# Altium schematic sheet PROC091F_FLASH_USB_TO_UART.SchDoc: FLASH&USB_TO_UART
size 431 x 279 mm; Date: Not shown in title block; ApprovedBy: Not shown in title block; CheckedBy: Not shown in title block; Author: Not shown in title block; CompanyName: Not shown in title block; DrawnBy: Antony/Bala; Engineer: Not shown in title block; Organization: Not shown in title block; Address1: Not shown in title block; Address2: Not shown in title block; Address3: Not shown in title block; Address4: Not shown in title block; DocumentNumber: 6; Revision: Use project parameter SCH_Rev; SheetNumber: 6; SheetTotal: 12; PageSetup: Record=PageOptions¦CenterHorizontal=True¦CenterVertical=True¦PrintScale=1.00¦XCorrection=1.00¦YCorrection=1.00¦PrintKind=0¦BorderSize=5000000¦LeftOffset=0¦BottomOffset=0¦Orientation=2¦PaperLength=1000¦PaperWidth=1000¦Scale=100¦PaperSource=15¦PrintQuality=600¦MediaType=1¦DitherType=10¦PaperKind=Letter¦PrintScaleMode=1
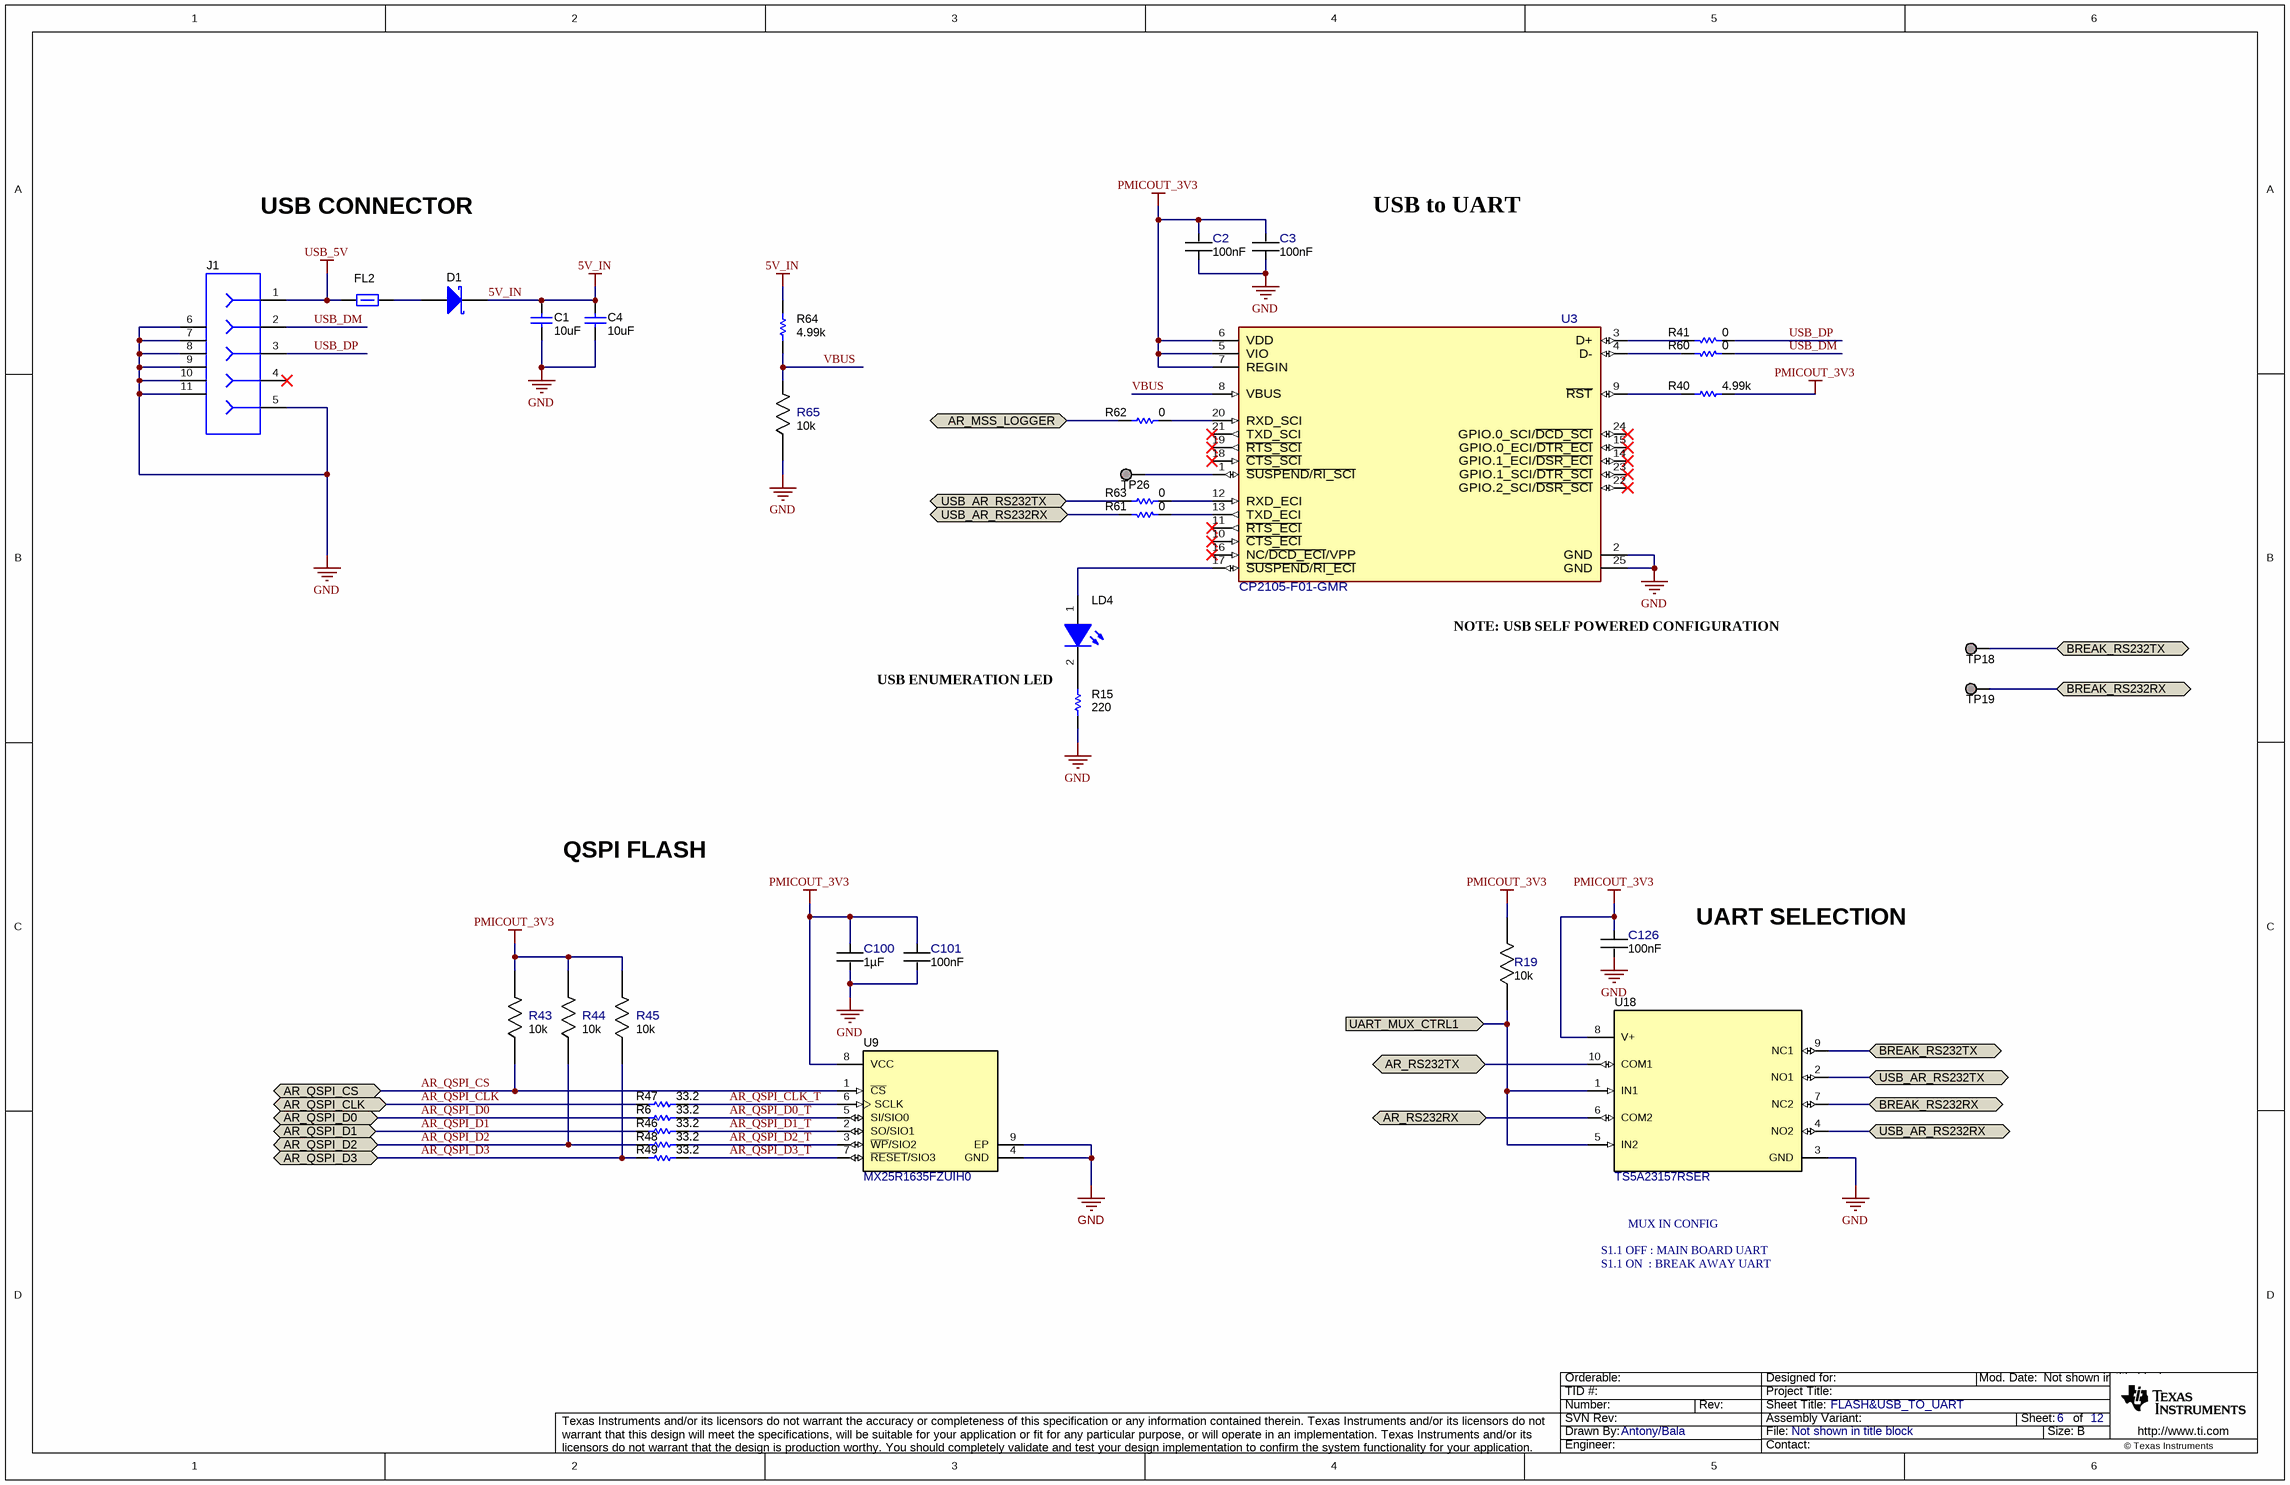
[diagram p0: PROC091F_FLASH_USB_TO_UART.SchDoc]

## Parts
C1  value 10uF  [0402_070]  (hidden comment: CL05A106MP5NUNC)
C2  Cap_F: 100nF  [FP-GRM033R6YA104KE14D_0201 (0603 Metric)-IPC_C]  (hidden comment: GRM033R6YA104KE14D)
C3  Cap_F: 100nF  [FP-GRM033R6YA104KE14D_0201 (0603 Metric)-IPC_C]  (hidden comment: GRM033R6YA104KE14D)
C4  value 10uF  [0402_070]  (hidden comment: CL05A106MP5NUNC)
C100  Cap_F: 1µF  [FP-CL03A105MO3NRNH_0201-IPC_C]  (hidden comment: CL03A105MO3NRNH)
C101  Cap_F: 100nF  [FP-GRM033R6YA104KE14D_0201 (0603 Metric)-IPC_C]  (hidden comment: GRM033R6YA104KE14D)
C126  Cap_F: 100nF  [FP-GRM033R6YA104KE14D_0201 (0603 Metric)-IPC_C]  (hidden comment: GRM033R6YA104KE14D)
D1  NSR20F30NXT5G  [DSN2_0603]  (value not drawn)
FL2  BLM15PD300SZ1D  [0402L]  (value not drawn)
J1  105017-0001  [CONN_105017-0001]  (value not drawn)
LD4  APHHS1005CGCK  [APHHS1005_Green]  (value not drawn)
R6  value 33.2  [0201L]  (hidden comment: CRCW020133R2FNED)
R15  value 220  [0201L]  (hidden comment: RC0201JR-07220RL)
R19  Res_ohm: 10k  [FP-RR0306P-103-D_0201-IPC_C]  (hidden comment: RR0306P-103-D)
R40  value 4.99k  [0201L]  (hidden comment: RC0201FR-074K99L)
R41  Res_ohm: 0  [FP-RC0201JR-070RL_0201 (0603 Metric)-MFG]  (hidden comment: RC0201JR-070RL)
R43  Res_ohm: 10k  [FP-RR0306P-103-D_0201-IPC_C]  (hidden comment: RR0306P-103-D)
R44  Res_ohm: 10k  [FP-RR0306P-103-D_0201-IPC_C]  (hidden comment: RR0306P-103-D)
R45  Res_ohm: 10k  [FP-RR0306P-103-D_0201-IPC_C]  (hidden comment: RR0306P-103-D)
R46  value 33.2  [0201L]  (hidden comment: CRCW020133R2FNED)
R47  value 33.2  [0201L]  (hidden comment: CRCW020133R2FNED)
R48  value 33.2  [0201L]  (hidden comment: CRCW020133R2FNED)
R49  value 33.2  [0201L]  (hidden comment: CRCW020133R2FNED)
R60  Res_ohm: 0  [FP-RC0201JR-070RL_0201 (0603 Metric)-MFG]  (hidden comment: RC0201JR-070RL)
R61  Res_ohm: 0  [FP-RC0201JR-070RL_0201 (0603 Metric)-MFG]  (hidden comment: RC0201JR-070RL)
R62  Res_ohm: 0  [FP-RC0201JR-070RL_0201 (0603 Metric)-MFG]  (hidden comment: RC0201JR-070RL)
R63  Res_ohm: 0  [FP-RC0201JR-070RL_0201 (0603 Metric)-MFG]  (hidden comment: RC0201JR-070RL)
R64  value 4.99k  [0201L]  (hidden comment: RC0201FR-074K99L)
R65  Res_ohm: 10k  [FP-RR0306P-103-D_0201-IPC_C]  (hidden comment: RR0306P-103-D)
TP18  TESTPOINT  [TP_25MIL-SMT]  (value not drawn)  (no BOM)
TP19  TESTPOINT  [TP_25MIL-SMT]  (value not drawn)  (no BOM)
TP26  TESTPOINT  [TP_25MIL-SMT]  (value not drawn)  (no BOM)
U3  CP2105-F01-GMR  [FP-CP2105-F01-GMR_QFN24-EP-IPC_A]
U9  MX25R1635FZUIH0  [USON-8L]
U18  TS5A23157RSER  [RSE0010A]

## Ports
AR_MSS_LOGGER (bidir), AR_QSPI_CLK (bidir), AR_QSPI_CS (bidir), AR_QSPI_D0 (bidir), AR_QSPI_D1 (bidir), AR_QSPI_D2 (bidir), AR_QSPI_D3 (bidir), AR_RS232RX (bidir), AR_RS232TX (bidir), BREAK_RS232RX (bidir), BREAK_RS232TX (bidir), UART_MUX_CTRL1 (in), USB_AR_RS232RX (bidir), USB_AR_RS232TX (bidir)

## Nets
5V_IN: C1.2 C4.1 D1.1(K) R64.1
GND: C1.1 C2.1 C3.1 C4.2 C100.2 C101.2 C126.2 J1.5 J1.6 J1.7 J1.8 J1.9 J1.10 J1.11 R15.1 R65.1 U3.2(GND) U3.25(GND) U9.4(GND) U9.9(EP) U18.3(GND)
PMICOUT_3V3: C2.2 C3.2 C100.1 C101.1 C126.1 R19.2 R40.1 R43.2 R44.2 R45.2 U3.5(VIO) U3.6(VDD) U3.7(REGIN) U9.8(VCC) U18.8(V+)
USB_5V: FL2.1 J1.1
AR_MSS_LOGGER: R62.2 ; port AR_MSS_LOGGER
AR_QSPI_CLK: R47.1 ; port AR_QSPI_CLK
AR_QSPI_CLK_T: R47.2 U9.6(SCLK)
AR_QSPI_CS: R43.1 U9.1(~{CS}) ; port AR_QSPI_CS
AR_QSPI_D0: R6.1 ; port AR_QSPI_D0
AR_QSPI_D0_T: R6.2 U9.5(SI/SIO0)
AR_QSPI_D1: R46.1 ; port AR_QSPI_D1
AR_QSPI_D1_T: R46.2 U9.2(SO/SIO1)
AR_QSPI_D2: R44.1 R48.1 ; port AR_QSPI_D2
AR_QSPI_D2_T: R48.2 U9.3(~{WP}/SIO2)
AR_QSPI_D3: R45.1 R49.1 ; port AR_QSPI_D3
AR_QSPI_D3_T: R49.2 U9.7(~{RESET}/SIO3)
AR_RS232RX: U18.6(COM2) ; port AR_RS232RX
AR_RS232TX: U18.10(COM1) ; port AR_RS232TX
BREAK_RS232RX: TP19.1 U18.7(NC2) ; port BREAK_RS232RX
BREAK_RS232TX: TP18.1 U18.9(NC1) ; port BREAK_RS232TX
UART_MUX_CTRL1: R19.1 U18.1(IN1) U18.5(IN2) ; port UART_MUX_CTRL1
USB_AR_RS232RX: R61.1 U18.4(NO2) ; port USB_AR_RS232RX
USB_AR_RS232TX: R63.2 U18.2(NO1) ; port USB_AR_RS232TX
USB_DM: J1.2 R60.2
USB_DP: J1.3 R41.2
VBUS: R64.2 R65.2 U3.8(VBUS)
NetD1_2: D1.2(A) FL2.2
NetLD4_1: LD4.1(A) U3.17(~{SUSPEND}/~{RI_ECI})
NetLD4_2: LD4.2(K) R15.2
NetR40_2: R40.2 U3.9(~{RST})
NetR41_1: R41.1 U3.3(D+)
NetR60_1: R60.1 U3.4(D-)
NetR61_2: R61.2 U3.13(TXD_ECI)
NetR62_1: R62.1 U3.20(RXD_SCI)
NetR63_1: R63.1 U3.12(RXD_ECI)
NetTP26_1: TP26.1 U3.1(~{SUSPEND}/~{RI_SCI})

Not connected (* = marked no-connect by the designer): J1 4*; U3 10(~{CTS_ECI})* 11(~{RTS_ECI})* 14(GPIO.1_ECI/~{DSR_ECI})* 15(GPIO.0_ECI/~{DTR_ECI})* 16(NC/~{DCD_ECI}/VPP)* 18(~{CTS_SCI})* 19(~{RTS_SCI})* 21(TXD_SCI)* 22(GPIO.2_SCI/~{DSR_SCI})* 23(GPIO.1_SCI/~{DTR_SCI})* 24(GPIO.0_SCI/~{DCD_SCI})*

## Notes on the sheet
- USB CONNECTOR
- USB to UART
- (near U3) NOTE: USB SELF POWERED CONFIGURATION
- USB ENUMERATION LED
- QSPI FLASH
- UART SELECTION
- MUX IN CONFIG
- S1.1 ON  : BREAK AWAY UART
- S1.1 OFF : MAIN BOARD UART

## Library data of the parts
C1 C4 = CMP-0006339-4: CAP, CERM, 10 uF, 10 V, +/- 20%, X5R, 0402; Manufacturer: Samsung Electro-Mechanics; AEC Category: Q200; AEC Qualified: N; Cap_Case: 0402; Cap_F: 10µF; SizeArea_mm2: 0.5; SizeAreaWB_mm2: 3; SizeX_mm: 1; SizeZ_mm: 0.6; TaMax_C: 85°C; TaMin_C: -55°C; U/M: EA; Value1: Unknown; Value2: 10V
C2 C3 C101 C126 = CMP-0086440-1: Cap Ceramic 0.1uF 35V X5R 10% Pad SMD 0201 85C T/R; Manufacturer: Murata Electronics North America; AEC Qualified: No; SizeZ_mm: 0.33mm; Symbol Name: SYM-GRM033R6YA104KE14D; TempCo: 15%
C100 = CMP-0086446-1: 1µF ±20% 16V Ceramic Capacitor X5R 0201; Manufacturer: Samsung Electro-Mechanics; AEC Qualified: No; SizeZ_mm: 0.39mm; Symbol Name: SYM-CL03A105MO3NRNH; TempCo: 15%
D1 = CMP-0028829-2: Diode, Schottky, 30 V, 2 A, 2-XFDFN; Manufacturer: ON Semiconductor; Value2: 0.48V; SizeY_mm: 0.8; Value: 30V; TJmax_C: 150°C; Green_Lifecycle: Not Set; SizeAreaWB_mm2: 4.68; Value1: 2A; SizeArea_mm2: 1.28; Green_REACh: Incomplete; AEC Category: Q101; SizeZ_mm: 0.31; Vf_V: 480mV; AEC Qualified: N; SizeX_mm: 1.6
FL2 = CMP-0078934-1: Inductor, Ferrite Bead, Ferrite, 2.2 A, 0.035 ohm, AEC-Q200 Grade 1, SMD; Manufacturer: MuRata; AEC Category: Q200; AEC Grade: 1; AEC Qualified: Y; DCR_ohm: 0.035; Imax_A: 2.2A; SizeArea_mm2: 0.5; SizeAreaWB_mm2: 3; SizeZ_mm: 0.6
J1 = CMP-0055293-1: Connector, Receptacle, Micro-USB Type B, R/A, Bottom Mount SMT; Manufacturer: Molex; CNHeader: FALSE; CompType: USB; CT: TRUE; Gender: Female; Green_Lifecycle: Active; Green_REACh: Passed
LD4 = CMP-0067682-2: LED, Green, SMD; Manufacturer: Kingbright; Angle: 120.0; Power_TotalModule: 75mW; SizeZ_mm: 0.6; Vf_V: 2.1V; Vr_V: 5V; Io_A: 20mA; Ir_A: 10µA; SizeArea_mm2: 0.5; SizeAreaWB_mm2: 3.0; SizeX_mm: 1.0; Tjmax_C: 85°C; Value1: 0.075W
R6 R46-R49 = CMP-0027275-3: RES, 33.2, 1%, 0.05 W, 0201; Manufacturer: Vishay-Dale; AEC Category: Q200; AEC Qualified: N; EIA_Code: E96; Power_W: 50mW; SizeArea_mm2: 0.18; SizeX_mm: 0.6; SizeY_mm: 0.3; SizeZ_mm: 0.26; TempCo: 200 ppm/C; Value2: 0.05W; Value_Code: 33R2
R15 = CMP-0027072-1: RES, 220, 5%, 0.05 W, 0201; Manufacturer: Yageo America; AEC Category: Q200; AEC Qualified: N; EIA_Code: E24; Power_W: 50mW; SizeArea_mm2: 0.18; SizeX_mm: 0.6; SizeY_mm: 0.3; SizeZ_mm: 0.26; TempCo: 200 ppm/C; U/M: EA; Value2: 0.05W; Value_Code: 220R; VDC_V: 25V
R19 R43-R45 R65 = CMP-0088002-1: 10 kOhms ±0.5% 0.05W, 1/20W Chip Resistor 0201 (0603 Metric)  Thin Film; Manufacturer: Susumu; AEC Qualified: No; Power_W: 50mW; SizeZ_mm: 0.26mm; Symbol Name: SYM-RR0306P-103-D; TempCo: 25ppm/°C; VDC_V: 15V
R40 R64 = CMP-0027745-1: RES, 4.99 k, 1%, 0.05 W, 0201; Manufacturer: Yageo America; AEC Category: Q200; AEC Qualified: N; EIA_Code: E96; Power_W: 50mW; SizeArea_mm2: 0.18; SizeX_mm: 0.6; SizeY_mm: 0.3; SizeZ_mm: 0.26; TempCo: 200 ppm/C; U/M: EA; Value2: 0.05W; Value_Code: 4k99; VDC_V: 25V
R41 R60-R63 = CMP-0086442-2: RES SMD 0 OHM JUMPER 1/20W 0201; Manufacturer: Yageo; AEC Qualified: No; Power_W: 50mW; SizeZ_mm: 0.26mm; TempCo: 200ppm/°C; Tolerance_%: 5%; VDC_V: 25V
TP18 TP19 TP26 = CMP-0078143-3: TEST POINT.  No entry in BOM.
U3 = CMP-0087172-1: I/O Controller Interface IC USB to Dual UART bridge; Manufacturer: Silicon Labs; SizeZ_mm: 0.8mm
U9 = CMP-0078466-1: ULTRA LOW POWER, 16M-BIT [x 1/x 2/x 4] CMOS MXSMIO (SERIAL MULTI I/O) FLASH MEMORY, SON-8; Manufacturer: Macronix International Co., LTD; SizeArea_mm2: 6; SizeAreaWB_mm2: 12; SizeX_mm: 3; SizeY_mm: 2; SizeZ_mm: 0.6
U18 = CMP-0074545-1: Dual 10-ohm SPDT Analog Switch, RSE0010A (UQFN-10); Alternate Manufacturer: Texas Instruments; CompType: IC; SizeArea_mm2: 3.0; SizeAreaWB_mm2: 7.5; SizeX_mm: 1.5; SizeY_mm: 2.0; SizeZ_mm: 0.6; U/M: EA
